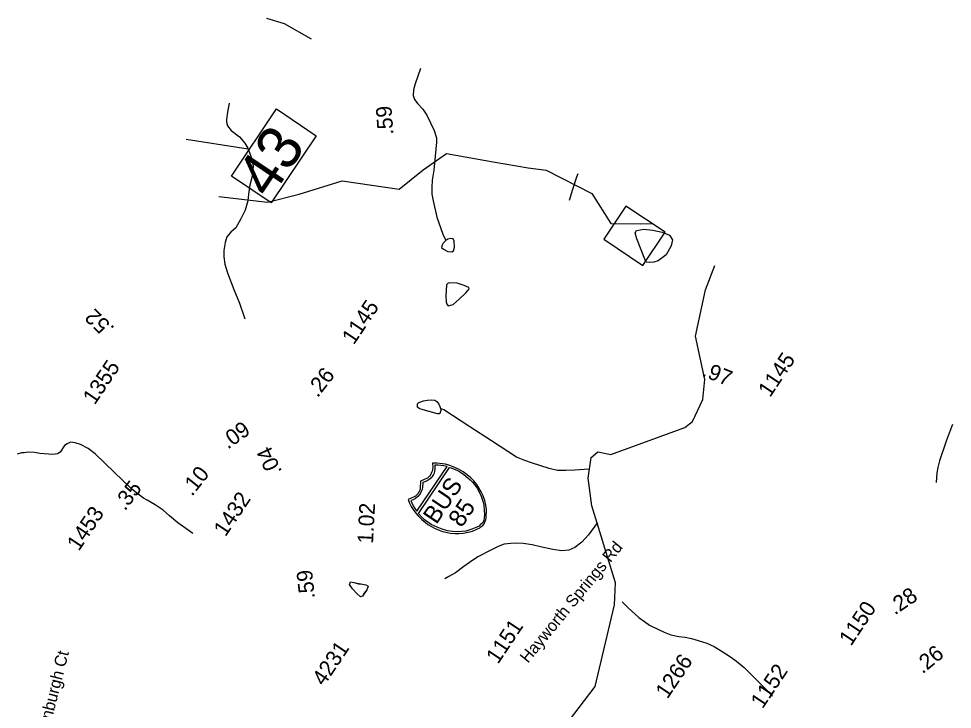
# Model space of a CAD drawing. Extents: x 1716282 to 1717158, y 799307 to 801078.
# Drawn here: x 1716655.9 to 1716763.9, y 799646.7 to 799726.5 of the extents above; entities that cross this region are included whole.
import ezdxf

# ---------------------------------------------------------------- set-up
doc = ezdxf.new("R2010")
doc.units = 0
for name, color, linetype in [('Exist Hydrographic Misc Water Feature', 7, 'Continuous'), ('Exist Hydrographic Pond Under 1500 Sq Ft', 7, 'Continuous'), ('Exist Road Non-System Type 51 Label', 7, 'Continuous'), ('Exist Road Primary Interstate Mileage Hundredths English Label', 7, 'Continuous'), ('Exist Road Primary Interstate Shield CELL', 7, 'Continuous'), ('Exist Road Primary Interstate Shield Number Label', 7, 'Continuous'), ('Exist Road Primary Interstate Structure Standard Bridge Number Label', 7, 'Continuous'), ('Exist Road Secondary Mileage Hundredths English Label', 7, 'Continuous'), ('Exist Road Secondary Mileage Tenths English Label', 7, 'Continuous'), ('Exist Road Secondary Structure Standard Bridge Number Label', 7, 'Continuous'), ('Exist Road Secondary Type 51 Number Label', 7, 'Continuous'), ('Exist Utilities Electrical Transmission Line', 7, 'Continuous')]:
    doc.layers.add(name, color=color, linetype=linetype)

msp = doc.modelspace()

# ---------------------------------------------------------------- linework, layer by layer
at = {"layer": 'Exist Hydrographic Misc Water Feature'}
for points in [[(1716689.78, 799724.17), (1716686.69, 799725.92), (1716684.63, 799726.54)], [(1716702.38, 799720.76), (1716701.76, 799718.98), (1716701.57, 799718.29), (1716701.55, 799717.64), (1716701.7, 799717.19), (1716702.1, 799716.7), (1716702.68, 799716.06), (1716703.14, 799715.39), (1716703.56, 799714.47), (1716703.96, 799713.61), (1716704.26, 799712.77), (1716704.23, 799712.26), (1716703.95, 799709.01), (1716703.75, 799707.85), (1716703.7, 799707), (1716703.7, 799706.23), (1716703.84, 799705.47), (1716704.28, 799703.59), (1716704.97, 799701.61), (1716705.34, 799700.87)], [(1716680.28, 799716.75), (1716680.1, 799715.71), (1716679.96, 799714.89), (1716679.96, 799714.58), (1716680.08, 799714.14), (1716680.5, 799713.61), (1716681.45, 799712.86), (1716682.09, 799712.14), (1716682.45, 799711.54), (1716682.75, 799710.74), (1716682.92, 799710.06), (1716683.04, 799709.52), (1716682.92, 799708.31), (1716682.67, 799707.28), (1716682.49, 799706.25), (1716682.45, 799705.47), (1716682.11, 799704.4), (1716681.61, 799703.37), (1716681.03, 799702.36), (1716680.48, 799701.86), (1716680.02, 799701.29), (1716679.81, 799700.63), (1716679.65, 799699.72), (1716679.66, 799699.01), (1716679.77, 799698.16), (1716680.07, 799697.15), (1716680.81, 799695.2), (1716681.46, 799693.63), (1716681.97, 799692.16), (1716682.08, 799691.81)], [(1716720.59, 799708.58), (1716720.44, 799708.21), (1716719.96, 799706.79), (1716719.57, 799705.5)], [(1716704.58, 799628.94), (1716713.22, 799629.76), (1716714.86, 799630.85), (1716717.17, 799634.24), (1716717.88, 799636.84), (1716718.33, 799642.38), (1716719.52, 799645.24), (1716722.58, 799649.29), (1716724.82, 799658.73), (1716724.93, 799661.29), (1716722.21, 799670.18), (1716721.78, 799673.4), (1716722.13, 799675.8), (1716722.88, 799676.45), (1716724.4, 799676.15), (1716732.95, 799679.24), (1716733.85, 799679.94), (1716735.05, 799682.49), (1716735.28, 799684.81), (1716734.19, 799689.8), (1716735.33, 799695.18), (1716736.44, 799697.97)], [(1716721.94, 799674.45), (1716721.32, 799674.38), (1716720.23, 799674.32), (1716719.19, 799674.29), (1716718.25, 799674.3), (1716717.27, 799674.51), (1716715.21, 799675.15), (1716714.45, 799675.43), (1716713.48, 799675.81), (1716710.59, 799677.7), (1716708.09, 799679.34), (1716705.1, 799681.28), (1716704.69, 799681.46)], [(1716763.88, 799679.6), (1716763.61, 799678.9), (1716763.15, 799677.66), (1716762.41, 799675.4), (1716762.2, 799674.63), (1716762.09, 799674), (1716762.01, 799672.9)], [(1716676.09, 799666.99), (1716675.25, 799667.57), (1716674.35, 799668.21), (1716673.36, 799669.03), (1716672.63, 799669.7), (1716671.72, 799670.32), (1716670.79, 799670.86), (1716670.38, 799671.09), (1716669.74, 799671.54), (1716669.02, 799672.13), (1716666.96, 799674.1), (1716664.77, 799676.19), (1716663.97, 799676.82), (1716663.09, 799677.28), (1716662.46, 799677.49), (1716661.95, 799677.56), (1716661.54, 799677.38), (1716661.23, 799677.18), (1716660.74, 799676.42), (1716660.43, 799676.21), (1716659.89, 799676.15), (1716658.4, 799676.23), (1716657.77, 799676.38), (1716657.03, 799676.39), (1716656.58, 799676.34), (1716656.28, 799676.31), (1716655.76, 799676.17)], [(1716722.87, 799668.26), (1716721.8, 799666.85), (1716721.03, 799665.98), (1716720.24, 799665.39), (1716719.53, 799665.07), (1716718.74, 799665.01), (1716717.69, 799665.16), (1716716.28, 799665.46), (1716715.3, 799665.67), (1716714.25, 799665.83), (1716713.53, 799665.86), (1716712.82, 799665.85), (1716712.07, 799665.77), (1716711.37, 799665.48), (1716710.53, 799665.07), (1716709.01, 799664.28), (1716708.04, 799663.64), (1716707.42, 799663.19), (1716706.43, 799662.45), (1716705.68, 799662.02), (1716705.22, 799661.77)], [(1716696.33, 799660.89), (1716696.2, 799660.49), (1716695.89, 799660.1), (1716695.67, 799659.76), (1716695.47, 799659.68), (1716695.03, 799660.06), (1716694.53, 799660.61), (1716694.2, 799661.11), (1716694.25, 799661.29), (1716694.32, 799661.39), (1716694.7, 799661.33), (1716695.23, 799661.18), (1716695.7, 799661.14), (1716696.07, 799661.07), (1716696.33, 799660.89)], [(1716696.33, 799660.89), (1716696.2, 799660.49), (1716695.67, 799659.76), (1716695.47, 799659.68), (1716695.03, 799660.06), (1716694.53, 799660.61), (1716694.2, 799661.11), (1716694.25, 799661.29), (1716694.32, 799661.39), (1716694.7, 799661.33), (1716695.7, 799661.14), (1716696.07, 799661.07), (1716696.33, 799660.89)], [(1716725.7, 799659.09), (1716726.42, 799658.39), (1716727.65, 799657.27), (1716728.28, 799656.8), (1716728.88, 799656.39), (1716729.82, 799655.92), (1716730.55, 799655.6), (1716731.35, 799655.27), (1716732.24, 799655.08), (1716732.99, 799655), (1716733.72, 799654.84), (1716734.49, 799654.63), (1716735.51, 799654.32), (1716736.34, 799653.94), (1716737.16, 799653.44), (1716738.25, 799652.73), (1716738.91, 799652.25), (1716739.82, 799651.48), (1716742.24, 799649.06), (1716743.09, 799648.19)]]:
    msp.add_lwpolyline(points, dxfattribs=at)
at = {"layer": 'Exist Hydrographic Pond Under 1500 Sq Ft'}
for points in [[(1716728.34, 799698.74), (1716727.39, 799701.07), (1716727.22, 799701.75), (1716727.35, 799702.03), (1716728.21, 799702.21), (1716729.25, 799702.07), (1716730.35, 799701.84), (1716731.17, 799701.48), (1716731.51, 799700.94), (1716731.37, 799700.28), (1716730.79, 799699.22), (1716729.88, 799698.52), (1716729.35, 799698.37), (1716728.83, 799698.35), (1716728.48, 799698.39), (1716728.34, 799698.74)], [(1716705.34, 799700.87), (1716705.02, 799700.59), (1716704.89, 799700.36), (1716704.84, 799700.08), (1716705.06, 799699.88), (1716705.57, 799699.59), (1716706.03, 799699.57), (1716706.19, 799699.7), (1716706.34, 799700.12), (1716706.27, 799700.79), (1716706.16, 799701.09), (1716705.89, 799701.12), (1716705.57, 799701.02), (1716705.34, 799700.87)], [(1716705.4, 799695.76), (1716705.32, 799694.48), (1716705.37, 799693.77), (1716705.42, 799693.5), (1716705.6, 799693.33), (1716705.9, 799693.39), (1716706.16, 799693.48), (1716706.85, 799694.08), (1716707.62, 799694.81), (1716707.9, 799695.15), (1716708.03, 799695.3), (1716707.98, 799695.46), (1716707.45, 799695.68), (1716706.64, 799695.94), (1716705.88, 799695.98), (1716705.58, 799695.95), (1716705.4, 799695.76)], [(1716704.69, 799681.46), (1716704.74, 799681.22), (1716704.61, 799680.88), (1716704.55, 799680.84), (1716704.37, 799680.83), (1716702.45, 799681.37), (1716702.25, 799681.44), (1716702.05, 799681.61), (1716702.05, 799681.75), (1716702.06, 799681.98), (1716702.22, 799682.16), (1716702.75, 799682.32), (1716703.2, 799682.41), (1716703.69, 799682.46), (1716704.05, 799682.42), (1716704.29, 799682.26), (1716704.51, 799681.96), (1716704.64, 799681.7), (1716704.69, 799681.46)]]:
    msp.add_lwpolyline(points, dxfattribs=at)
at = {"layer": 'Exist Road Primary Interstate Shield CELL'}
for points in [[(1716709.74, 799668.11), (1716709.8, 799668.24), (1716709.88, 799668.41), (1716709.93, 799668.59), (1716709.97, 799668.81), (1716709.99, 799669.16), (1716710.01, 799669.44), (1716710.01, 799669.77), (1716709.94, 799670.28), (1716709.82, 799670.82), (1716709.63, 799671.34), (1716709.42, 799671.8), (1716709.15, 799672.26), (1716708.89, 799672.67), (1716708.55, 799673.08), (1716708.2, 799673.44), (1716707.79, 799673.77), (1716707.34, 799674.12), (1716706.78, 799674.45), (1716706.17, 799674.72), (1716705.77, 799674.86), (1716705.27, 799675.01), (1716704.93, 799675.07), (1716704.3, 799675.13), (1716703.8, 799675.14), (1716703.81, 799674.66), (1716703.78, 799674.37), (1716703.75, 799674.2), (1716703.68, 799674.05), (1716703.55, 799673.78), (1716703.44, 799673.63), (1716703.31, 799673.51), (1716703.2, 799673.4), (1716703.09, 799673.34), (1716702.38, 799673.04), (1716702.37, 799672.27), (1716702.35, 799672.13), (1716702.3, 799671.99), (1716702.25, 799671.86), (1716702.14, 799671.68), (1716702.04, 799671.54), (1716701.92, 799671.41), (1716701.82, 799671.32), (1716701.68, 799671.23), (1716700.97, 799670.92), (1716701.13, 799670.5), (1716701.32, 799670.12), (1716701.63, 799669.64), (1716701.89, 799669.3), (1716702.11, 799669.04), (1716702.55, 799668.6), (1716702.96, 799668.25), (1716703.26, 799668.03), (1716704.08, 799667.57), (1716704.55, 799667.38), (1716704.94, 799667.24), (1716705.86, 799667.04), (1716706.41, 799666.99), (1716706.82, 799666.98), (1716707.32, 799667.02), (1716707.57, 799667.06), (1716708.41, 799667.28), (1716708.89, 799667.48), (1716709.24, 799667.66), (1716709.38, 799667.76), (1716709.59, 799667.93)], [(1716701.26, 799670.81), (1716701.38, 799670.55), (1716701.55, 799670.21), (1716701.75, 799669.9), (1716701.98, 799669.56), (1716705.47, 799674.76), (1716705.11, 799674.82), (1716704.76, 799674.87), (1716704.42, 799674.9), (1716704.07, 799674.9), (1716704.06, 799674.48), (1716704.01, 799674.2), (1716703.96, 799673.99), (1716703.89, 799673.83), (1716703.76, 799673.59), (1716703.69, 799673.49), (1716703.41, 799673.23), (1716703.18, 799673.07), (1716702.91, 799672.96), (1716702.65, 799672.9), (1716702.62, 799672.32), (1716702.58, 799672.09), (1716702.49, 799671.84), (1716702.37, 799671.59), (1716702.09, 799671.26), (1716701.81, 799671.05), (1716701.53, 799670.89)], [(1716705.74, 799674.62), (1716705.93, 799674.58), (1716706.3, 799674.43), (1716706.58, 799674.31), (1716706.9, 799674.15), (1716707.39, 799673.81), (1716707.88, 799673.44), (1716708.15, 799673.19), (1716708.39, 799672.94), (1716708.64, 799672.65), (1716708.95, 799672.24), (1716709.17, 799671.82), (1716709.39, 799671.32), (1716709.56, 799670.84), (1716709.62, 799670.63), (1716709.7, 799670.27), (1716709.75, 799669.67), (1716709.78, 799669.24), (1716709.75, 799668.77), (1716709.71, 799668.55), (1716709.62, 799668.32), (1716709.5, 799668.16), (1716709.31, 799668), (1716709.16, 799667.86), (1716708.73, 799667.64), (1716708.34, 799667.48), (1716707.63, 799667.26), (1716707.15, 799667.21), (1716706.64, 799667.2), (1716706.13, 799667.23), (1716705.5, 799667.32), (1716704.91, 799667.48), (1716704.31, 799667.71), (1716703.62, 799668.05), (1716703.23, 799668.3), (1716702.87, 799668.58), (1716702.7, 799668.74), (1716702.49, 799668.95), (1716702.18, 799669.29)]]:
    msp.add_lwpolyline(points, close=True, dxfattribs=at)
at = {"layer": 'Exist Road Primary Interstate Structure Standard Bridge Number Label'}
msp.add_line((1716730.67, 799701.83), (1716726.15, 799704.86), dxfattribs=at)
msp.add_lwpolyline([(1716726.15, 799704.86), (1716723.58, 799701.02), (1716728.11, 799697.99), (1716730.67, 799701.83)], dxfattribs=at)
at = {"layer": 'Exist Road Secondary Structure Standard Bridge Number Label'}
msp.add_line((1716675.3, 799712.59), (1716682.47, 799711.48), dxfattribs=at)
msp.add_lwpolyline([(1716680.54, 799708.32), (1716685.73, 799716.09), (1716690.34, 799713), (1716685.14, 799705.24)], close=True, dxfattribs=at)
at = {"layer": 'Exist Utilities Electrical Transmission Line'}
msp.add_lwpolyline([(1716679.07, 799705.97), (1716684.71, 799705.32), (1716688.36, 799706.22), (1716693.32, 799707.8), (1716699.92, 799706.81), (1716702.7, 799709.04), (1716705.41, 799710.94), (1716710.8, 799709.98), (1716714.84, 799709.3), (1716716.93, 799709.02), (1716722.2, 799706.3), (1716724.38, 799702.83), (1716727.88, 799702.8), (1716729.17, 799702.83)], dxfattribs=at)

# ---------------------------------------------------------------- texts
at = {"layer": 'Exist Road Non-System Type 51 Label'}
for s, rotation, p in [('Hayworth Springs Rd', 50.6744, (1716714.82, 799651.92)), ('Edinburgh Ct', 75.8693, (1716659.13, 799642.81))]:
    msp.add_text(s, height=1.3775, rotation=rotation, dxfattribs=at).set_placement(p)
at = {"layer": 'Exist Road Primary Interstate Mileage Hundredths English Label'}
for s, rotation, p in [('.59', 94.228, (1716699.27, 799713.15)), ('1.02', 86.924, (1716696.9, 799665.77))]:
    msp.add_text(s, height=1.812, rotation=rotation, dxfattribs=at).set_placement(p)
at = {"layer": 'Exist Road Primary Interstate Shield Number Label'}
for s, p in [('BUS', (1716704.24, 799667.96)), ('85', (1716707.15, 799667.58))]:
    msp.add_text(s, height=2.03, rotation=56.2051, dxfattribs=at).set_placement(p)
at = {"layer": 'Exist Road Secondary Mileage Hundredths English Label'}
for s, rotation, p in [('.52', 136.4312, (1716667.12, 799690.8)), ('.26', 52.0562, (1716690.5, 799682.63)), ('.97', 338.1117, (1716734.84, 799685.25)), ('.04', 114.6529, (1716686.42, 799674.16)), ('.59', 96.106, (1716690.2, 799659.52)), ('.28', 34.1279, (1716757.23, 799657.51)), ('.26', 39.2308, (1716760.43, 799650.7))]:
    msp.add_text(s, height=1.812, rotation=rotation, dxfattribs=at).set_placement(p)
at = {"layer": 'Exist Road Secondary Mileage Tenths English Label'}
for s, rotation, p in [('.09', 35.3635, (1716680.12, 799676.68)), ('.10', 51.5549, (1716675.98, 799671.22)), ('.35', 52.7263, (1716668.23, 799669.53))]:
    msp.add_text(s, height=1.812, rotation=rotation, dxfattribs=at).set_placement(p)
at = {"layer": 'Exist Road Secondary Structure Standard Bridge Number Label'}
msp.add_text('43', height=5.075, rotation=56.2051, dxfattribs=at).set_placement((1716685.01, 799705.55))
at = {"layer": 'Exist Road Secondary Type 51 Number Label'}
for s, p in [('1145', (1716694.68, 799688.73)), ('1355', (1716664.73, 799681.78)), ('1145', (1716742.8, 799682.65)), ('1432', (1716679.85, 799666.54)), ('1453', (1716662.89, 799664.87)), ('1150', (1716752.16, 799653.89)), ('1151', (1716711.35, 799651.81)), ('4231', (1716691.24, 799649.27)), ('1266', (1716730.94, 799647.78)), ('1152', (1716741.94, 799646.64))]:
    msp.add_text(s, height=1.812, rotation=56.2051, dxfattribs=at).set_placement(p)

doc.saveas('drawing.dxf')
